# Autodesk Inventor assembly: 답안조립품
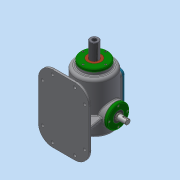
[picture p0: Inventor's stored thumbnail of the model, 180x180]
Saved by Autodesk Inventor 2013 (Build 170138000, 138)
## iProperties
Created: 2019-10
Part Number: 답안조립품
Document SubType Name: Assembly
Designer: dgall
Author: dgall
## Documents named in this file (17)
- C:\Users\dgall\Desktop\391004V1014\답안조립품.iam
- C:\Users\dgall\Desktop\391004V1014\개스킷 A.ipt
- C:\Users\dgall\Desktop\391004V1014\개스킷 B.ipt
- C:\Users\dgall\Desktop\391004V1014\고정플레이트.ipt
- C:\Users\dgall\Desktop\391004V1014\베어링 6205.ipt
- 베어링 6205.ipt
- C:\Users\dgall\Desktop\391004V1014\본체.ipt
- C:\Users\dgall\Desktop\391004V1014\볼트 M4x0.7.ipt
- C:\Users\dgall\Desktop\391004V1014\부시.ipt
- C:\Users\dgall\Desktop\391004V1014\상부커버.ipt
- C:\Users\dgall\Desktop\391004V1014\슬라이드 커버.ipt
- C:\Users\dgall\Desktop\391004V1014\슬라이드.ipt
- C:\Users\dgall\Desktop\391004V1014\오일 실 25 38 8.ipt
- C:\Users\dgall\Desktop\391004V1014\육각머리볼트 M4.ipt
- C:\Users\dgall\Desktop\391004V1014\축 커버.ipt
- C:\Users\dgall\Desktop\391004V1014\편심축.ipt
- C:\Users\dgall\Desktop\391004V1014\가변스프링.ipt
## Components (17 placed, 5 different names)
1. 개스킷 A:1 — 각도:8, 각도:9
2. 개스킷 B:1 — 각도:6
3. 고정플레이트:1
4. 개스킷 B:2 — 각도:3
5. 가변스프링:1
6. M4x0.7:1 — 각도:4
7. M4x0.7:3
8. M4x0.7:4
9. M4x0.7:5
10. M4x0.7:2 — 각도:7
11. M4x0.7:6
12. M4x0.7:7
13. M4x0.7:8
14. M4x0.7:9 — 각도:14
15. M4x0.7:10
16. M4x0.7:11
17. M4x0.7:12
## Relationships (7: Angle 7)
- 각도:3 [Angle]: 개스킷 B:2
- 각도:4 [Angle]: M4x0.7:1
- 각도:6 [Angle]: 개스킷 B:1
- 각도:7 [Angle]: M4x0.7:2
- 각도:8 [Angle]: 개스킷 A:1
- 각도:9 [Angle]: 개스킷 A:1
- 각도:14 [Angle]: M4x0.7:9
